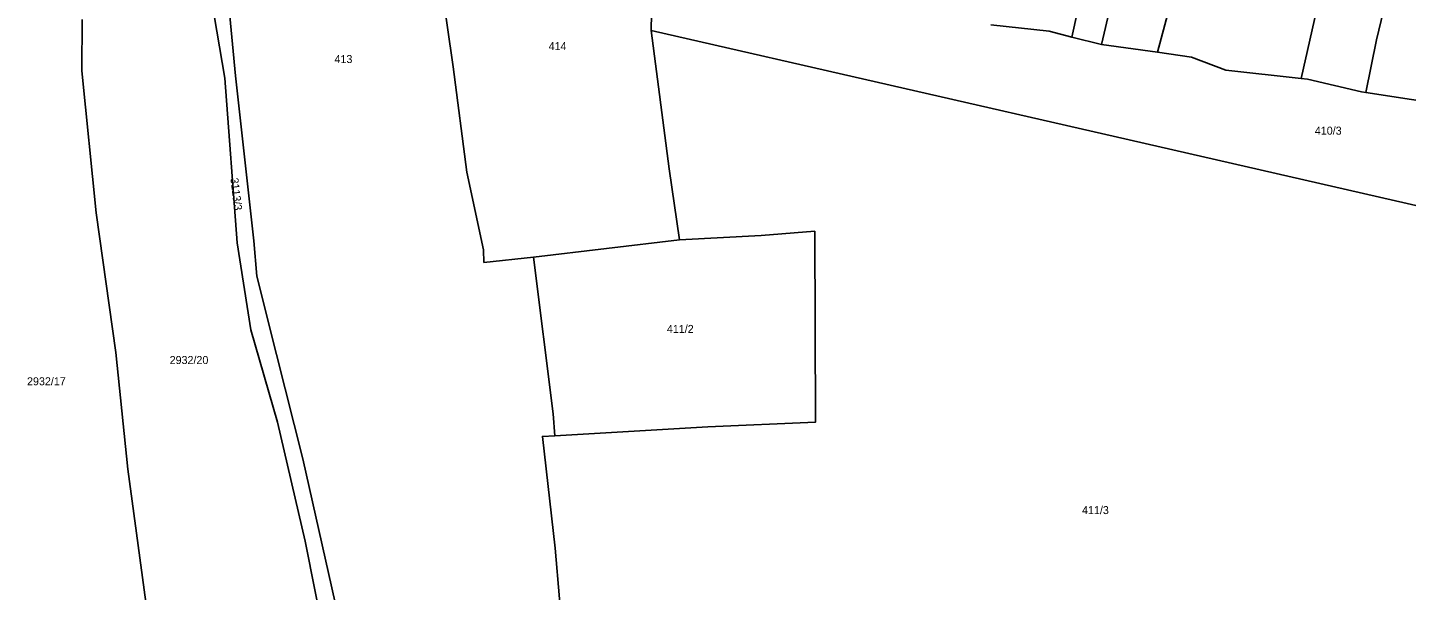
# Model space of a CAD drawing. Extents: x -776734 to -748832, y -1118122 to -976986.
# Drawn here: x -753945.5 to -753652.6, y -1113955.7 to -1113836.1 of the extents above; entities that cross this region are included whole.
import ezdxf

# ---------------------------------------------------------------- set-up
doc = ezdxf.new("R2010")
doc.units = 0
doc.layers.add('KM_Hranice parcel', color=7, linetype='Continuous')
doc.layers.add('KM_Parcelní čísla', color=7, linetype='Continuous')

msp = doc.modelspace()

# ---------------------------------------------------------------- linework, layer by layer
at = {"layer": 'KM_Hranice parcel'}
for p, q in [((-753812.36, -1113806.13), (-753813.05, -1113836.73)), ((-753717.39, -1113839.76), (-753723.69, -1113838.15)), ((-753705.53, -1113841.39), (-753717.39, -1113839.76)), ((-753807.04, -1113881.24), (-753838.04, -1113884.87))]:
    msp.add_line(p, q, dxfattribs=at)
for points in [[(-753723.69, -1113838.15), (-753712.38, -1113786.79), (-753702.79, -1113743.75)], [(-753717.39, -1113839.76), (-753708.91, -1113803.45), (-753695.73, -1113745.08)], [(-753705.53, -1113841.39), (-753687.61, -1113774.51), (-753679.85, -1113747.92)], [(-753675.01, -1113846.97), (-753669.5, -1113822.48), (-753659.45, -1113779.09), (-753653.33, -1113755.04)], [(-753661.29, -1113849.89), (-753659, -1113838.76), (-753652.01, -1113809.61), (-753639.44, -1113758.53)], [(-753599.81, -1113768.38), (-753632.17, -1113854.41), (-753661.29, -1113849.89)], [(-753838.04, -1113884.87), (-753848.55, -1113886.03), (-753848.63, -1113883.35), (-753852.16, -1113866.88), (-753855.1, -1113844.46), (-753858.94, -1113817.84), (-753861.16, -1113800.66)], [(-753903.52, -1113823.18), (-753901.35, -1113846.36), (-753897.43, -1113881.42), (-753896.81, -1113888.95), (-753892.58, -1113905.57), (-753886.99, -1113927.7), (-753871.99, -1113994.49), (-753867.56, -1114002.99)], [(-753880.21, -1113976.91), (-753886.51, -1113945.21), (-753892.41, -1113919.97), (-753898.08, -1113900.3), (-753900.93, -1113881.86), (-753903.59, -1113846.87), (-753906.96, -1113826.83)], [(-753915.44, -1113988.98), (-753919.79, -1113962.33), (-753924.17, -1113929.95), (-753926.71, -1113905.18), (-753930.88, -1113875.47), (-753933.97, -1113845.34), (-753933.88, -1113834.39)], [(-753723.69, -1113838.15), (-753728.54, -1113836.91), (-753740.88, -1113835.54)], [(-753813.05, -1113836.73), (-753809.22, -1113866.16), (-753807.04, -1113881.24)], [(-753813.05, -1113836.73), (-753711.5, -1113859.99), (-753612.02, -1113882.78)], [(-753675.01, -1113846.97), (-753691.02, -1113845.15), (-753698.25, -1113842.39), (-753705.53, -1113841.39)], [(-753661.29, -1113849.89), (-753662.18, -1113849.75), (-753673.67, -1113847.12), (-753675.01, -1113846.97)], [(-753833.5, -1113922.82), (-753801, -1113920.92), (-753778.12, -1113919.91), (-753778.3, -1113879.41), (-753789.69, -1113880.29), (-753807.04, -1113881.24)], [(-753838.04, -1113884.87), (-753833.83, -1113918.14), (-753833.5, -1113922.82)], [(-753833.5, -1113922.82), (-753836.15, -1113922.97), (-753833.41, -1113946.72), (-753832.54, -1113957.5), (-753827.91, -1113996.51)]]:
    msp.add_lwpolyline(points, dxfattribs=at)

# ---------------------------------------------------------------- texts
at = {"layer": 'KM_Parcelní čísla'}
for s, p in [('414', (-753834.82, -1113840.93)), ('413', (-753880.29, -1113843.67)), ('410/3', (-753672.09, -1113858.88)), ('411/2', (-753809.7, -1113900.99)), ('2932/20', (-753915.3, -1113907.6)), ('2932/17', (-753945.59, -1113912.11)), ('411/3', (-753721.53, -1113939.47))]:
    msp.add_text(s, height=1.7, dxfattribs=at).set_placement(p)
msp.add_text('3113/3', height=1.7, rotation=277, dxfattribs=at).set_placement((-753902.413, -1113868.153))

doc.saveas('drawing.dxf')
